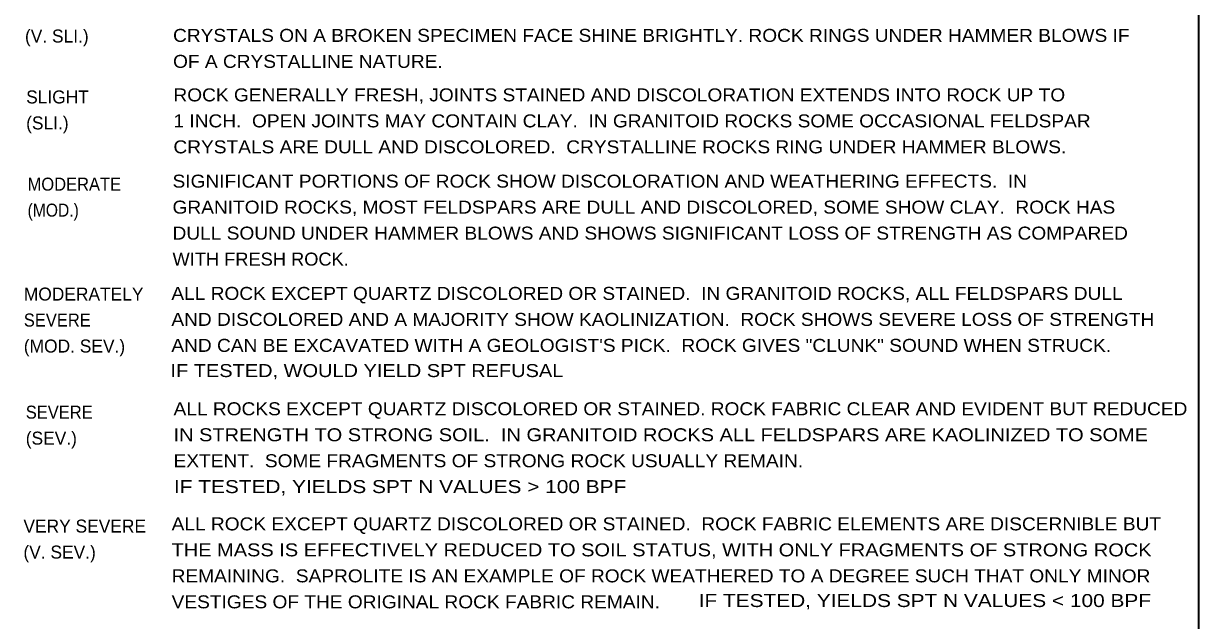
# Model space of a CAD drawing. Extents: x 2137492.6 to 2137529.1, y 2137475.8 to 2137563.
# Drawn here: x 2137510.87 to 2137519.91, y 2137548.89 to 2137553.49 of the extents above; entities that cross this region are included whole.
import ezdxf

# ---------------------------------------------------------------- set-up
doc = ezdxf.new("R2010")
doc.units = 0
doc.header["$LTSCALE"] = 0.04
doc.layers.add('1', color=7, linetype='Continuous', lineweight=35)
doc.layers.add('2', color=7, linetype='Continuous')

msp = doc.modelspace()

# ---------------------------------------------------------------- linework, layer by layer
at = {"layer": '1'}
msp.add_line((2137519.912, 2137558.218), (2137519.912, 2137539.727), dxfattribs=at)

# ---------------------------------------------------------------- texts
at = {"layer": '2'}
for s, p in [('(V. SLI.)', (2137510.877, 2137553.339)), ('SLIGHT', (2137510.886, 2137552.87)), ('(SLI.)', (2137510.886, 2137552.67)), ('MODERATELY', (2137510.868, 2137551.353)), ('(MOD. SEV.)', (2137510.868, 2137550.953)), ('(SEV.)', (2137510.883, 2137550.244)), ('VERY SEVERE', (2137510.865, 2137549.567)), ('(V. SEV.)', (2137510.865, 2137549.367))]:
    msp.add_text(s, height=0.1, dxfattribs=at).set_placement(p)
for s, width, p in [('CRYSTALS ON A BROKEN SPECIMEN FACE SHINE BRIGHTLY. ROCK RINGS UNDER HAMMER BLOWS IF ', 1.1, (2137512.017, 2137553.344)), ('OF A CRYSTALLINE NATURE.', 1.1, (2137512.017, 2137553.144)), ('ROCK GENERALLY FRESH, JOINTS STAINED AND DISCOLORATION EXTENDS INTO ROCK UP TO ', 1.1, (2137512.02, 2137552.886)), ('1 INCH.  OPEN JOINTS MAY CONTAIN CLAY.  IN GRANITOID ROCKS SOME OCCASIONAL FELDSPAR ', 1.1, (2137512.02, 2137552.686)), ('CRYSTALS ARE DULL AND DISCOLORED.  CRYSTALLINE ROCKS RING UNDER HAMMER BLOWS.', 1.1, (2137512.02, 2137552.486)), ('MODERATE', 0.95, (2137510.897, 2137552.199)), ('SIGNIFICANT PORTIONS OF ROCK SHOW DISCOLORATION AND WEATHERING EFFECTS.  IN ', 1.1, (2137512.013, 2137552.222)), ('(MOD.)', 0.9, (2137510.897, 2137551.999)), ('GRANITOID ROCKS, MOST FELDSPARS ARE DULL AND DISCOLORED, SOME SHOW CLAY.  ROCK HAS ', 1.1, (2137512.013, 2137552.022)), ('DULL SOUND UNDER HAMMER BLOWS AND SHOWS SIGNIFICANT LOSS OF STRENGTH AS COMPARED ', 1.1, (2137512.013, 2137551.822)), ('WITH FRESH ROCK.', 1.05, (2137512.013, 2137551.622)), ('ALL ROCK EXCEPT QUARTZ DISCOLORED OR STAINED.  IN GRANITOID ROCKS, ALL FELDSPARS DULL ', 1.1, (2137512.004, 2137551.358)), ('SEVERE', 0.95, (2137510.868, 2137551.153)), ('AND DISCOLORED AND A MAJORITY SHOW KAOLINIZATION.  ROCK SHOWS SEVERE LOSS OF STRENGTH ', 1.1, (2137512.004, 2137551.158)), ('AND CAN BE EXCAVATED WITH A GEOLOGIST\'S PICK.  ROCK GIVES "CLUNK" SOUND WHEN STRUCK.', 1.1, (2137512.004, 2137550.958)), ('IF TESTED, WOULD YIELD SPT REFUSAL', 1.15, (2137511.997, 2137550.764)), ('SEVERE', 0.95, (2137510.883, 2137550.444)), ('ALL ROCKS EXCEPT QUARTZ DISCOLORED OR STAINED. ROCK FABRIC CLEAR AND EVIDENT BUT REDUCED ', 1.1, (2137512.021, 2137550.47)), ('IN STRENGTH TO STRONG SOIL.  IN GRANITOID ROCKS ALL FELDSPARS ARE KAOLINIZED TO SOME ', 1.15, (2137512.021, 2137550.27)), ('EXTENT.  SOME FRAGMENTS OF STRONG ROCK USUALLY REMAIN.', 1.1, (2137512.021, 2137550.07)), ('IF TESTED, YIELDS SPT N VALUES > 100 BPF', 1.2, (2137512.024, 2137549.871)), ('ALL ROCK EXCEPT QUARTZ DISCOLORED OR STAINED.  ROCK FABRIC ELEMENTS ARE DISCERNIBLE BUT ', 1.1, (2137512.006, 2137549.584)), ('THE MASS IS EFFECTIVELY REDUCED TO SOIL STATUS, WITH ONLY FRAGMENTS OF STRONG ROCK ', 1.15, (2137512.006, 2137549.384)), ('REMAINING.  SAPROLITE IS AN EXAMPLE OF ROCK WEATHERED TO A DEGREE SUCH THAT ONLY MINOR ', 1.1, (2137512.006, 2137549.184)), ('IF TESTED, YIELDS SPT N VALUES < 100 BPF', 1.2, (2137516.064, 2137548.994)), ('VESTIGES OF THE ORIGINAL ROCK FABRIC REMAIN.', 1.1, (2137512.006, 2137548.984))]:
    msp.add_text(s, height=0.1, dxfattribs=dict(at, width=width)).set_placement(p)

doc.saveas('drawing.dxf')
